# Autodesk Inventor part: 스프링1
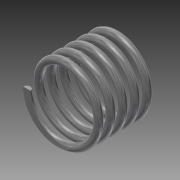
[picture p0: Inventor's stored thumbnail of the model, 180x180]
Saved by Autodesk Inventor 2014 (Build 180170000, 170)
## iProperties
Created: 2016-10
Part Number: 스프링1
Material: 강철, 탄소
Document SubType Name: Modeling
Designer: 703-16
Density: 7.87 g/cm^3
Appearance: 반연마
Mass: 6.81239 g
Surface Area: 17.6676 cm^2
Volume: 0.865614 cm^3
Author: 703-16
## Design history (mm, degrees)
sketch "스케치1"
  geometry: L1 (0, 0)-(-9, 0); L2 (-9, 0)-(-9, 16.67); L3 (-9, 16.67)-(0, 16.67); L4 (0, 16.67)-(0, 0); C1 r 1 at (-9, 0)
  constraints: 8 end point, 2 parallel, 1 centre point, 1 coincident, 1 horizontal, 1 perpendicular
  dimensions: "d0" = 16.66987 distance of L3.end L1.start (derived); "d1" = 2 diameter of C1; "d2" = 18 diameter of L2 L4
feature "코일1" sketch "스케치1" pitch "d3" = 10; turns "d5" = 5; dims "d4" = 16.66987 (= d0), "d6" = 0, angle "d7" = 90 deg, angle "d8" = 90 deg, "d9" = 0, "d10" = 0
node "작업 평면1"
sketch "스케치2"
  geometry: L1 (0, 0)-(-2, 0) reference; 1 further point
  constraints: 1 horizontal alignment
extrude "돌출1" cut sketch "스케치2" distance "d11" = 10; taper "d12" = 0 deg
sketch "스케치3"
  geometry: L1 (8, 0)-(10, 0) reference; 1 further point
  constraints: 1 horizontal alignment
extrude "돌출2" cut sketch "스케치3" distance "d13" = 10; taper "d14" = 0 deg
node "솔리드1"
node "절단 모서리 투영1"
node "절단 모서리 투영2"
